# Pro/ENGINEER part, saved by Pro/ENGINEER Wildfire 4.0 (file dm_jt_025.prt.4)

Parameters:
  METRIC = "NO"

Other parameters: PITCH, DRILL_POINT_ANGLE, DRILL_DEPTH, DRILL_DIAMETER, THREAD_DIAMETER, THREADS_PER_INCH, THREAD_DEPTH, THREAD_LENGTH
